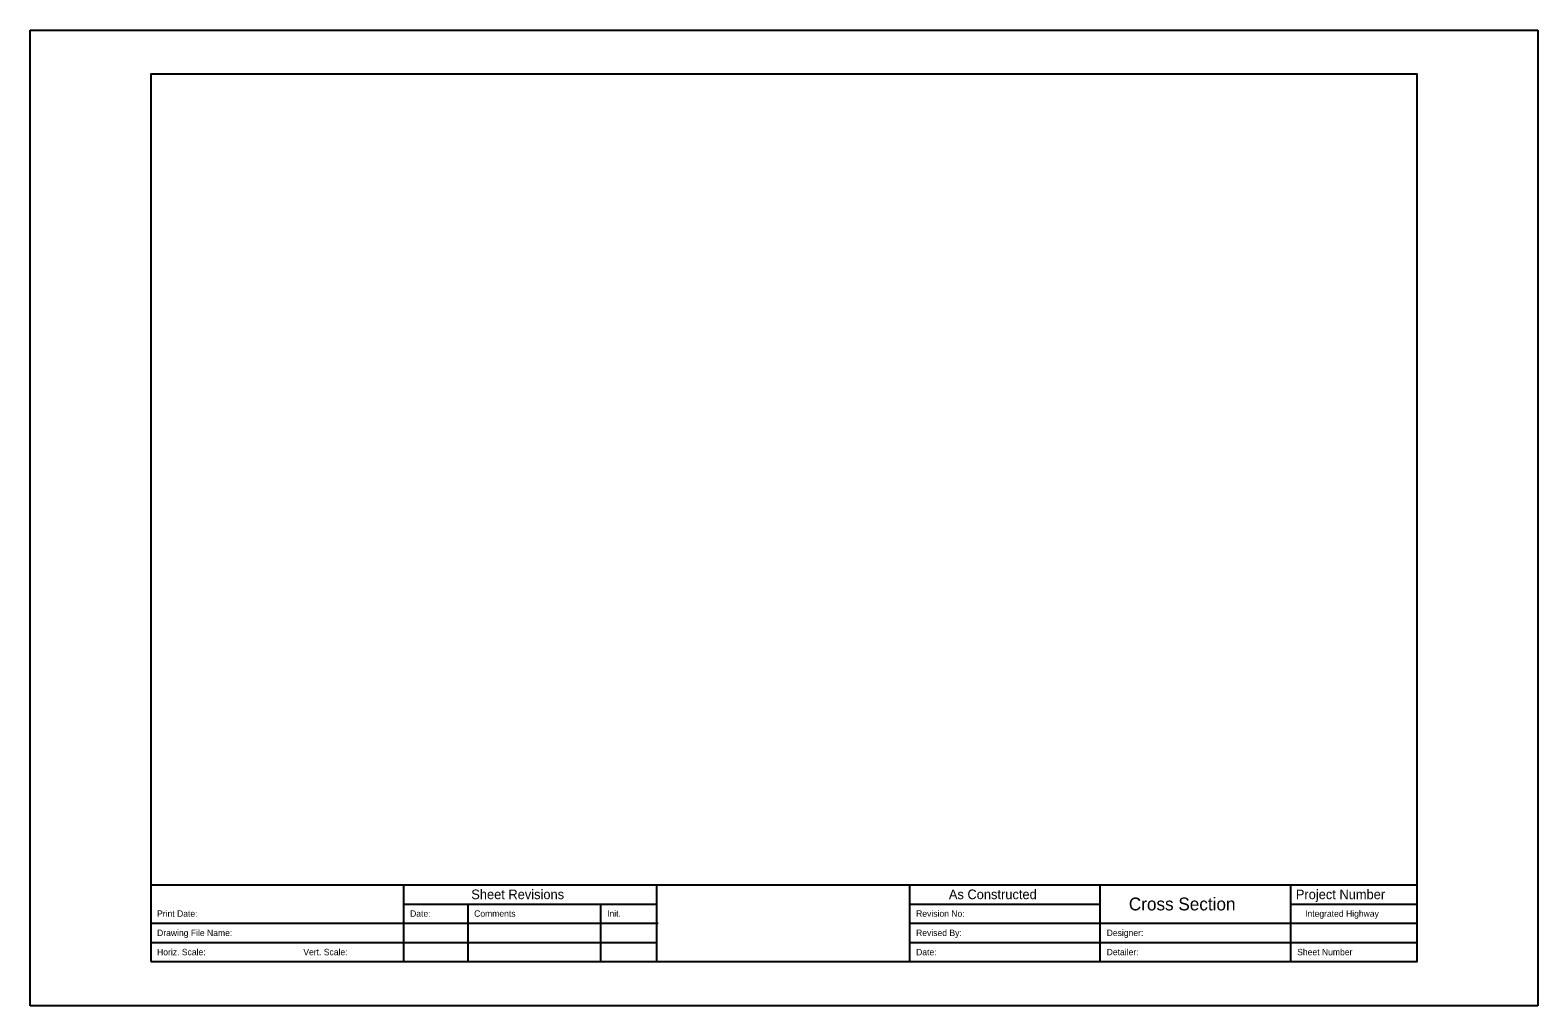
# Model space of a CAD drawing. Extents: x 0 to 2.83, y 0 to 1.83.
import ezdxf

# ---------------------------------------------------------------- set-up
doc = ezdxf.new("R2010")
doc.units = 0
doc.layers.add('Draft_Sheet', color=7, linetype='Continuous')

msp = doc.modelspace()

# ---------------------------------------------------------------- linework, layer by layer
at = {"layer": 'Draft_Sheet'}
for p, q in [((0, 1.833), (2.8331, 1.833)), ((0, 0), (0, 1.833)), ((2.8331, 1.833), (2.8331, 0)), ((0.2265, 0.2274), (2.6066, 0.2274)), ((0.7019, 0.083), (0.7019, 0.2274)), ((1.1773, 0.083), (1.1773, 0.2274)), ((1.6528, 0.083), (1.6528, 0.2274)), ((2.0108, 0.083), (2.0108, 0.2274)), ((2.3689, 0.083), (2.3689, 0.2274)), ((0.7019, 0.1913), (1.1773, 0.1913)), ((0.8223, 0.1913), (0.8223, 0.083)), ((1.072, 0.1913), (1.072, 0.083)), ((1.6528, 0.1913), (2.0108, 0.1913)), ((2.3689, 0.1913), (2.6066, 0.1913)), ((0.2265, 0.1552), (1.1804, 0.1552)), ((1.6528, 0.1552), (2.6066, 0.1552)), ((0.2265, 0.1191), (1.1773, 0.1191)), ((1.6528, 0.1191), (2.6066, 0.1191)), ((2.8331, 0), (0, 0))]:
    msp.add_line(p, q, dxfattribs=at)
msp.add_lwpolyline([(0.2265, 0.083), (2.6066, 0.083), (2.6066, 1.75), (0.2265, 1.75)], close=True, dxfattribs=at)

# ---------------------------------------------------------------- texts
for s, height, p in [('Sheet Revisions', 0.018054, (0.8289, 0.2004)), ('As Constructed', 0.018054, (1.7264, 0.2004)), ('Cross Section', 0.024072, (2.0646, 0.1793)), ('Project Number', 0.018054, (2.3784, 0.2004)), ('Print Date:', 0.012036, (0.2385, 0.1673)), ('Date:', 0.01204, (0.714, 0.1673)), ('Comments', 0.01204, (0.8343, 0.1673)), ('Init.', 0.01204, (1.0841, 0.1673)), ('Revision No:', 0.012036, (1.6648, 0.1673)), ('Integrated Highway', 0.012036, (2.3957, 0.1673)), ('Drawing File Name:', 0.012036, (0.2385, 0.1311)), ('Revised By:', 0.012036, (1.6648, 0.1311)), ('Designer:', 0.01204, (2.0229, 0.1311)), ('Horiz. Scale:', 0.012036, (0.2385, 0.095)), ('Vert. Scale:', 0.012036, (0.5133, 0.095)), ('Date:', 0.01204, (1.6648, 0.095)), ('Detailer:', 0.01204, (2.0229, 0.095)), ('Sheet Number', 0.012036, (2.3809, 0.095))]:
    msp.add_text(s, height=height, dxfattribs=at).set_placement(p)

doc.saveas('drawing.dxf')
